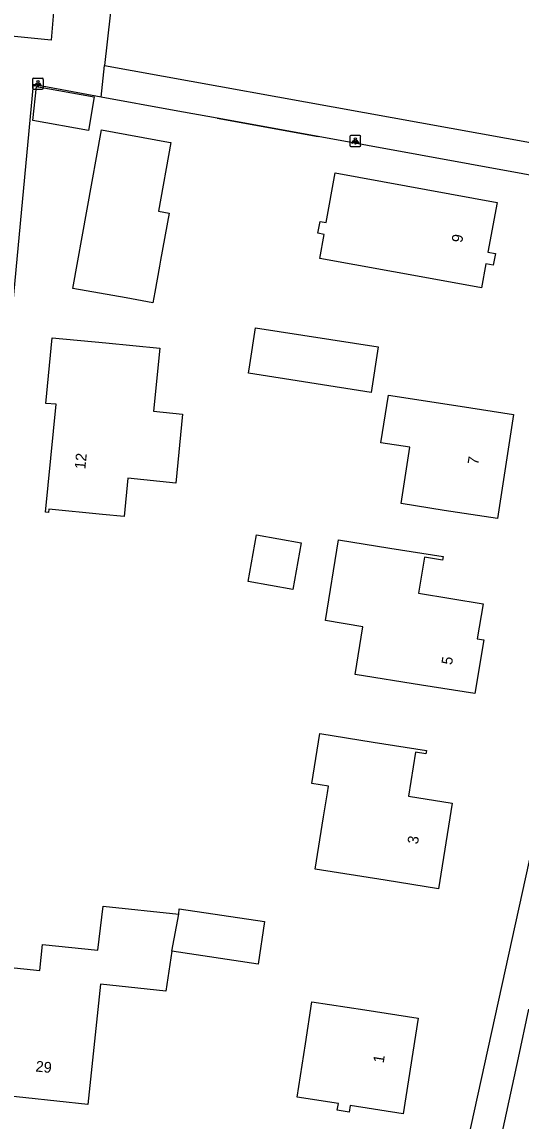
# Model space of a CAD drawing. Extents: x 162186 to 163152, y 385513 to 386513.
# Drawn here: x 162411.3 to 162457.5, y 385728.8 to 385830.6 of the extents above; entities that cross this region are included whole.
import ezdxf

# ---------------------------------------------------------------- set-up
doc = ezdxf.new("R2010")
doc.units = 0
for name, color, linetype in [('IMGEO_Lichtpunt', 7, 'Continuous'), ('IMGEO_Muur', 7, 'Continuous'), ('IMGEO_Pand', 7, 'Continuous'), ('IMGEO_Pand_nummerreeks', 7, 'Continuous'), ('IMGEO_Rijbaan_lokaal_gesloten', 7, 'Continuous'), ('IMGEO_Voetpad_open', 7, 'Continuous')]:
    doc.layers.add(name, color=color, linetype=linetype)

msp = doc.modelspace()

# ---------------------------------------------------------------- linework, layer by layer
at = {"layer": 'IMGEO_Lichtpunt'}
for p, q in [((162412.27, 385825.32), (162412.27, 385824.51)), ((162412.27, 385825.32), (162412.27, 385824.51)), ((162413.17, 385825.41), (162412.37, 385825.41)), ((162413.17, 385825.41), (162412.37, 385825.41)), ((162413.27, 385824.51), (162413.27, 385825.32)), ((162413.27, 385824.51), (162413.27, 385825.32)), ((162412.37, 385824.42), (162413.17, 385824.42)), ((162412.37, 385824.42), (162413.17, 385824.42)), ((162441.65, 385820.01), (162441.65, 385819.21)), ((162441.65, 385820.01), (162441.65, 385819.21)), ((162442.55, 385820.11), (162441.74, 385820.11)), ((162442.55, 385820.11), (162441.74, 385820.11)), ((162442.64, 385819.21), (162442.64, 385820.01)), ((162442.64, 385819.21), (162442.64, 385820.01)), ((162441.74, 385819.11), (162442.55, 385819.11)), ((162441.74, 385819.11), (162442.55, 385819.11))]:
    msp.add_line(p, q, dxfattribs=at)
for points in [[(162412.65, 385824.98), (162412.68, 385824.95), (162412.5, 385824.69), (162412.46, 385824.72), (162412.65, 385824.98)], [(162412.75, 385824.93), (162412.8, 385824.93), (162412.8, 385824.61), (162412.75, 385824.61), (162412.75, 385824.93)], [(162412.86, 385824.95), (162412.9, 385824.98), (162413.08, 385824.72), (162413.04, 385824.69), (162412.86, 385824.95)], [(162442.02, 385819.68), (162442.06, 385819.65), (162441.87, 385819.39), (162441.83, 385819.42), (162442.02, 385819.68)], [(162442.12, 385819.63), (162442.17, 385819.63), (162442.17, 385819.31), (162442.12, 385819.31), (162442.12, 385819.63)], [(162442.23, 385819.65), (162442.27, 385819.68), (162442.46, 385819.41), (162442.42, 385819.39), (162442.23, 385819.65)]]:
    msp.add_lwpolyline(points, dxfattribs=at)
for centre in [(162412.77, 385825.12), (162442.15, 385819.81)]:
    msp.add_circle(centre, 0.0994, dxfattribs=at)
for centre, start, end in [((162412.37, 385825.32), 90, 180), ((162412.37, 385825.32), 90, 180), ((162413.17, 385825.32), 0, 90), ((162413.17, 385825.32), 0, 90), ((162412.37, 385824.51), 180, 270), ((162412.37, 385824.51), 180, 270), ((162413.17, 385824.51), 270, 0), ((162413.17, 385824.51), 270, 360), ((162441.74, 385820.01), 90, 180), ((162441.74, 385820.01), 90, 180), ((162442.55, 385820.01), 0, 90), ((162442.55, 385820.01), 0, 90), ((162441.74, 385819.21), 180, 270), ((162441.74, 385819.21), 180, 270), ((162442.55, 385819.21), 270, 0), ((162442.55, 385819.21), 270, 360)]:
    msp.add_arc(centre, 0.0946, start, end, dxfattribs=at)
at = {"layer": 'IMGEO_Muur'}
msp.add_lwpolyline([(162429.36, 385821.72), (162438.72, 385820.02)], dxfattribs=at)
at = {"layer": 'IMGEO_Pand'}
for points in [[(162412.63, 385824.67), (162417.98, 385823.71), (162417.46, 385820.57), (162412.3, 385821.5), (162412.63, 385824.67)], [(162416, 385805.96), (162418.66, 385820.63), (162424.84, 385819.51), (162425.07, 385819.47), (162423.92, 385813.11), (162424.91, 385812.93), (162424.12, 385808.58), (162424.02, 385808.01), (162423.58, 385805.6), (162423.4, 385804.62), (162420.92, 385805.07), (162416, 385805.96)], [(162438.86, 385808.74), (162439.26, 385810.95), (162438.69, 385811.06), (162438.89, 385812.16), (162439.45, 385812.06), (162440.29, 385816.65), (162455.28, 385813.91), (162454.43, 385809.31), (162455.11, 385809.18), (162454.91, 385808.11), (162454.24, 385808.23), (162453.84, 385806.01), (162448.92, 385806.9), (162438.86, 385808.74)], [(162432.9, 385802.31), (162444.27, 385800.55), (162443.61, 385796.32), (162432.25, 385798.09), (162432.37, 385798.89), (162432.9, 385802.31)], [(162413.77, 385785.5), (162413.74, 385785.21), (162413.47, 385785.23), (162414.44, 385795.22), (162413.49, 385795.31), (162414.09, 385801.39), (162419.06, 385800.9), (162424.04, 385800.42), (162423.47, 385794.57), (162426.14, 385794.31), (162425.52, 385787.93), (162421.09, 385788.37), (162420.75, 385784.82), (162418.74, 385785.02), (162413.77, 385785.5)], [(162445.21, 385796.08), (162451.86, 385795.04), (162456.8, 385794.27), (162455.3, 385784.63), (162450.36, 385785.4), (162446.39, 385786.02), (162447.2, 385791.25), (162444.52, 385791.66), (162445.21, 385796.08)], [(162432.24, 385778.8), (162432.99, 385783.12), (162437.12, 385782.4), (162436.37, 385778.08), (162432.24, 385778.8)], [(162440.6, 385782.68), (162445.35, 385781.91), (162450.28, 385781.11), (162450.23, 385780.78), (162448.54, 385781.05), (162448, 385777.72), (162453.97, 385776.75), (162453.44, 385773.5), (162454.03, 385773.41), (162453.22, 385768.42), (162448.28, 385769.22), (162442.13, 385770.21), (162442.85, 385774.62), (162439.39, 385775.19), (162440.6, 385782.68)], [(162438.87, 385764.72), (162443.8, 385763.93), (162448.73, 385763.14), (162448.69, 385762.85), (162447.72, 385763.01), (162447.07, 385758.92), (162451.11, 385758.27), (162449.84, 385750.34), (162444.9, 385751.13), (162438.43, 385752.17), (162439.21, 385757), (162439.57, 385759.22), (162439.66, 385759.84), (162438.12, 385760.09), (162438.87, 385764.72)], [(162425.16, 385744.56), (162424.61, 385740.86), (162418.57, 385741.5), (162417.39, 385730.38), (162408.73, 385731.3), (162409.26, 385736.27), (162409.98, 385743.1), (162412.94, 385742.79), (162413.2, 385745.19), (162418.31, 385744.65), (162418.79, 385748.75), (162425.8, 385748.01)], [(162425.8, 385748.01), (162425.85, 385748.49), (162433.74, 385747.31), (162433.15, 385743.35), (162425.16, 385744.56)], [(162425.16, 385744.56), (162425.8, 385748.01)], [(162443.03, 385739.13), (162447.97, 385738.36), (162446.59, 385729.5), (162441.68, 385730.27), (162441.59, 385729.67), (162440.48, 385729.84), (162440.58, 385730.47), (162436.76, 385731.06), (162437.53, 385736), (162438.13, 385739.89), (162443.03, 385739.13)]]:
    msp.add_lwpolyline(points, dxfattribs=at)
at = {"layer": 'IMGEO_Rijbaan_lokaal_gesloten'}
msp.add_lwpolyline([(162455.27, 385725.59), (162457.25, 385734.69), (162458.21, 385739.19)], dxfattribs=at)
at = {"layer": 'IMGEO_Voetpad_open'}
for points in [[(162422.51, 385858.46), (162418.94, 385826.59)], [(162414.26, 385832.29), (162413.98, 385828.95), (162409.68, 385829.38)], [(162418.61, 385823.68), (162418.94, 385826.59)], [(162418.94, 385826.59), (162472.2, 385816.96)], [(162418.61, 385823.68), (162412.31, 385824.84), (162410.31, 385803.39)], [(162471.71, 385814.01), (162438.72, 385820.02), (162429.36, 385821.72), (162425.37, 385822.44), (162418.61, 385823.68)], [(162451.43, 385721.99), (162451.54, 385722.3), (162451.61, 385722.62), (162457.63, 385750), (162471.71, 385814.01)]]:
    msp.add_lwpolyline(points, dxfattribs=at)

# ---------------------------------------------------------------- texts
at = {"layer": 'IMGEO_Pand_nummerreeks'}
for s, rotation, p in [('9', 79.7054, (162452.03, 385810.14)), ('12', 84.4368, (162417.15, 385789.17)), ('7', 81.1547, (162453.52, 385789.57)), ('5', 80.7929, (162451.09, 385771.04)), ('3', 80.8615, (162447.94, 385754.43)), ('29', 353.9521, (162412.51, 385733.43)), ('1', 81.159, (162444.77, 385734.16))]:
    msp.add_text(s, height=1, rotation=rotation, dxfattribs=at).set_placement(p)

doc.saveas('drawing.dxf')
